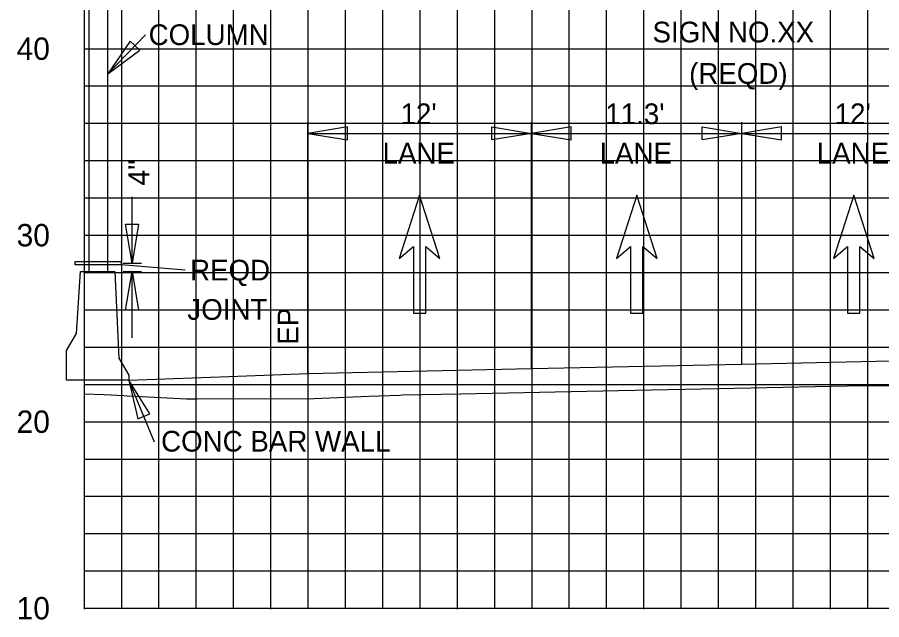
# Model space of a CAD drawing. Extents: x 1797809 to 2198143, y 249608 to 1237864.
# Drawn here: x 2195654.19 to 2195700.54, y 1237162.49 to 1237194.79 of the extents above; entities that cross this region are included whole.
import ezdxf

# ---------------------------------------------------------------- set-up
doc = ezdxf.new("R2010")
doc.units = 0
for name, color, linetype in [('3', 7, 'Continuous'), ('31', 7, 'Continuous'), ('60', 7, 'Continuous'), ('Default', 7, 'Continuous'), ('DESIGN - SHEET - Light Grid', 7, 'Continuous'), ('DESIGN - TRAFFIC CONTROL PERMANENT - Signs', 7, 'Continuous'), ('GSDIMS', 7, 'Continuous'), ('GSSHT', 7, 'Continuous'), ('Level 28', 7, 'Continuous'), ('Level 55', 7, 'Continuous')]:
    doc.layers.add(name, color=color, linetype=linetype)

msp = doc.modelspace()

# ---------------------------------------------------------------- linework, layer by layer
at = {"layer": '3'}
for p, q in [((2195658.037, 1237181.164), (2195658.037, 1237205.554)), ((2195659.037, 1237181.164), (2195659.037, 1237205.554)), ((2195659.037, 1237191.753), (2195661.071, 1237193.849)), ((2195669.761, 1237175.691), (2195669.761, 1237189.173)), ((2195681.762, 1237175.955), (2195681.762, 1237189.173)), ((2195693.037, 1237176.198), (2195693.037, 1237189.167)), ((2195660.344, 1237181.608), (2195660.344, 1237185.162)), ((2195663.2, 1237181.233), (2195659.753, 1237181.52)), ((2195659.862, 1237181.608), (2195660.844, 1237181.608)), ((2195659.862, 1237181.164), (2195660.844, 1237181.164)), ((2195660.344, 1237177.611), (2195660.344, 1237181.164)), ((2195661.547, 1237172), (2195660.17, 1237175.34))]:
    msp.add_line(p, q, dxfattribs=at)
msp.add_lwpolyline([(2195659.753, 1237181.52), (2195657.285, 1237181.52), (2195657.285, 1237181.697), (2195659.753, 1237181.697)], close=True, dxfattribs=at)
at = {"layer": '60'}
for p, q in [((2195657.787, 1237163.106), (2195657.787, 1237223.106)), ((2195657.787, 1237163.046), (2195657.787, 1237163.106)), ((2195657.787, 1237163.106), (2195787.787, 1237163.106)), ((2195667.787, 1237163.046), (2195667.787, 1237163.106)), ((2195677.787, 1237163.046), (2195677.787, 1237163.106)), ((2195687.787, 1237163.046), (2195687.787, 1237163.106)), ((2195697.787, 1237163.046), (2195697.787, 1237163.106))]:
    msp.add_line(p, q, dxfattribs=at)
at = {"layer": 'Default'}
msp.add_lwpolyline([(2195656.83, 1237176.924), (2195657.36, 1237177.834), (2195657.582, 1237181.164), (2195659.417, 1237181.164), (2195659.639, 1237176.51), (2195660.17, 1237175.6), (2195660.17, 1237175.34), (2195656.83, 1237175.34)], close=True, dxfattribs=at)
at = {"layer": 'DESIGN - SHEET - Light Grid'}
msp.add_lwpolyline([(2195657.787, 1237174.595), (2195658.845, 1237174.571), (2195659.91, 1237174.502), (2195660.089, 1237174.492), (2195660.504, 1237174.473), (2195663.264, 1237174.34), (2195663.831, 1237174.34), (2195670.107, 1237174.345), (2195673.042, 1237174.469), (2195673.596, 1237174.491), (2195674.692, 1237174.534), (2195674.847, 1237174.54), (2195677.95, 1237174.603), (2195686.428, 1237174.773), (2195693.523, 1237174.914), (2195698.688, 1237175.026), (2195709.231, 1237175.1), (2195710.338, 1237175.108), (2195710.888, 1237175.097), (2195716.393, 1237174.989), (2195721.708, 1237174.885), (2195722.245, 1237174.874), (2195723.166, 1237174.852), (2195735.286, 1237174.563)], dxfattribs=at)
at = {"layer": 'DESIGN - TRAFFIC CONTROL PERMANENT - Signs'}
msp.add_lwpolyline([(2195660.17, 1237175.34), (2195666.017, 1237175.541), (2195669.761, 1237175.691), (2195681.762, 1237175.955), (2195693.037, 1237176.198), (2195705.037, 1237176.457), (2195714.45, 1237176.66), (2195717.037, 1237176.715), (2195730.646, 1237177.009), (2195731.643, 1237176.969), (2195731.677, 1237176.936), (2195731.717, 1237176.896), (2195740.647, 1237176.539), (2195742.647, 1237176.459), (2195743.525, 1237176.424), (2195746.147, 1237176.319), (2195746.15, 1237176.318), (2195762.036, 1237171.022)], dxfattribs=at)
at = {"layer": 'GSDIMS'}
for p, q in [((2195669.761, 1237188.559), (2195681.762, 1237188.559)), ((2195681.762, 1237188.559), (2195693.037, 1237188.559)), ((2195693.037, 1237188.559), (2195705.037, 1237188.559))]:
    msp.add_line(p, q, dxfattribs=at)
for points in [[(2195659.037, 1237191.753), (2195660.76, 1237193.025), (2195660.246, 1237193.503)], [(2195669.761, 1237188.559), (2195671.889, 1237188.212), (2195671.889, 1237188.907)], [(2195681.762, 1237188.559), (2195679.633, 1237188.212), (2195679.633, 1237188.907)], [(2195681.762, 1237188.559), (2195683.89, 1237188.212), (2195683.89, 1237188.907)], [(2195693.037, 1237188.559), (2195690.908, 1237188.212), (2195690.908, 1237188.907)], [(2195693.037, 1237188.559), (2195695.165, 1237188.212), (2195695.165, 1237188.907)], [(2195660.344, 1237181.608), (2195659.989, 1237183.691), (2195660.698, 1237183.691)], [(2195660.344, 1237181.164), (2195660.698, 1237179.081), (2195659.989, 1237179.081)], [(2195660.17, 1237175.34), (2195660.651, 1237173.254), (2195661.294, 1237173.535)]]:
    msp.add_lwpolyline(points, close=True, dxfattribs=at)
at = {"layer": 'GSSHT'}
for p, q in [((2195659.787, 1237163.106), (2195659.787, 1237223.106)), ((2195661.787, 1237163.106), (2195661.787, 1237223.106)), ((2195663.787, 1237163.106), (2195663.787, 1237223.106)), ((2195665.787, 1237163.106), (2195665.787, 1237223.106)), ((2195667.787, 1237163.106), (2195667.787, 1237223.106)), ((2195669.787, 1237163.106), (2195669.787, 1237223.106)), ((2195671.787, 1237163.106), (2195671.787, 1237223.106)), ((2195673.787, 1237163.106), (2195673.787, 1237223.106)), ((2195675.787, 1237163.106), (2195675.787, 1237223.106)), ((2195677.787, 1237163.106), (2195677.787, 1237223.106)), ((2195679.787, 1237163.106), (2195679.787, 1237223.106)), ((2195681.787, 1237163.106), (2195681.787, 1237223.106)), ((2195683.787, 1237163.106), (2195683.787, 1237223.106)), ((2195685.787, 1237163.106), (2195685.787, 1237223.106)), ((2195687.787, 1237163.106), (2195687.787, 1237223.106)), ((2195689.787, 1237163.106), (2195689.787, 1237223.106)), ((2195691.787, 1237163.106), (2195691.787, 1237223.106)), ((2195693.787, 1237163.106), (2195693.787, 1237223.106)), ((2195695.787, 1237163.106), (2195695.787, 1237223.106)), ((2195697.787, 1237163.106), (2195697.787, 1237223.106)), ((2195699.787, 1237163.106), (2195699.787, 1237223.106)), ((2195657.787, 1237193.106), (2195787.787, 1237193.106)), ((2195657.787, 1237191.106), (2195787.787, 1237191.106)), ((2195657.787, 1237189.106), (2195787.787, 1237189.106)), ((2195657.787, 1237187.106), (2195787.787, 1237187.106)), ((2195657.787, 1237185.106), (2195787.787, 1237185.106)), ((2195657.787, 1237183.106), (2195787.787, 1237183.106)), ((2195657.787, 1237181.106), (2195787.787, 1237181.106)), ((2195657.787, 1237179.106), (2195787.787, 1237179.106)), ((2195657.787, 1237177.106), (2195787.787, 1237177.106)), ((2195657.787, 1237175.106), (2195787.787, 1237175.106)), ((2195657.787, 1237173.106), (2195787.787, 1237173.106)), ((2195657.787, 1237171.106), (2195787.787, 1237171.106)), ((2195657.787, 1237169.106), (2195787.787, 1237169.106)), ((2195657.787, 1237167.106), (2195787.787, 1237167.106)), ((2195657.787, 1237165.106), (2195787.787, 1237165.106)), ((2195657.787, 1237163.106), (2195787.787, 1237163.106))]:
    msp.add_line(p, q, dxfattribs=at)
at = {"layer": 'Level 28'}
for p, q in [((2195675.761, 1237185.25), (2195674.672, 1237181.852)), ((2195676.85, 1237181.852), (2195675.761, 1237185.25)), ((2195687.399, 1237185.25), (2195686.31, 1237181.852)), ((2195688.489, 1237181.852), (2195687.399, 1237185.25)), ((2195699.037, 1237185.25), (2195697.948, 1237181.852)), ((2195700.126, 1237181.852), (2195699.037, 1237185.25)), ((2195674.672, 1237181.852), (2195675.434, 1237182.491)), ((2195675.434, 1237182.491), (2195675.434, 1237178.92)), ((2195676.088, 1237178.92), (2195676.088, 1237182.491)), ((2195676.088, 1237182.491), (2195676.85, 1237181.852)), ((2195686.31, 1237181.852), (2195687.072, 1237182.491)), ((2195687.072, 1237182.491), (2195687.072, 1237178.92)), ((2195687.726, 1237178.92), (2195687.726, 1237182.491)), ((2195687.726, 1237182.491), (2195688.489, 1237181.852)), ((2195697.948, 1237181.852), (2195698.71, 1237182.491)), ((2195698.71, 1237182.491), (2195698.71, 1237178.92)), ((2195699.364, 1237178.92), (2195699.364, 1237182.491)), ((2195699.364, 1237182.491), (2195700.126, 1237181.852)), ((2195675.434, 1237178.92), (2195676.088, 1237178.92)), ((2195687.072, 1237178.92), (2195687.726, 1237178.92)), ((2195698.71, 1237178.92), (2195699.364, 1237178.92))]:
    msp.add_line(p, q, dxfattribs=at)

# ---------------------------------------------------------------- texts
at = {"layer": '31'}
for s, p in [('40', (2195654.154, 1237192.506)), ('30', (2195654.154, 1237182.506)), ('20', (2195654.154, 1237172.506)), ('10', (2195654.154, 1237162.506))]:
    msp.add_text(s, height=1.2, dxfattribs=at).set_placement(p)
at = {"layer": 'Level 55'}
for s, height, p in [('SIGN NO.XX', 1.1105, (2195688.249, 1237193.442)), ('COLUMN', 1.1105, (2195661.233, 1237193.3)), ('(REQD)', 1.1105, (2195690.212, 1237191.221)), ("12'", 1.1105, (2195674.74, 1237189.059)), ("11.3'", 1.1105, (2195685.72, 1237189.059)), ("12'", 1.1105, (2195698.016, 1237189.059)), ('LANE', 1.1105, (2195673.776, 1237186.949)), ('LANE', 1.1105, (2195685.414, 1237186.949)), ('LANE', 1.1105, (2195697.051, 1237186.949)), ('REQD', 1.1105, (2195663.456, 1237180.678)), ('JOINT', 1.1105, (2195663.308, 1237178.568)), ('CONC BAR WALL', 1.11046, (2195661.902, 1237171.504))]:
    msp.add_text(s, height=height, dxfattribs=at).set_placement(p)
for s, height, p in [('4"', 1.1346, (2195661.27, 1237185.77)), ('EP', 1.1105, (2195669.261, 1237177.235))]:
    msp.add_text(s, height=height, rotation=90, dxfattribs=at).set_placement(p)

doc.saveas('drawing.dxf')
